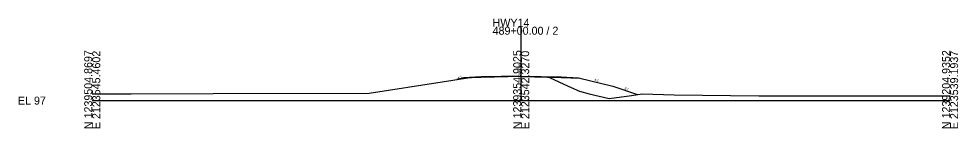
# Model space of a CAD drawing. Extents: x -26 to 303, y -10 to 11521.
# Drawn here: x -25.7 to 302.8, y 490.3 to 528.7 of the extents above; entities that cross this region are included whole.
import ezdxf

# ---------------------------------------------------------------- set-up
doc = ezdxf.new("R2010")
doc.units = 0
for name, color, linetype in [('XS_CELL', 7, 'Continuous'), ('XS_P_FINISHED_GRADE', 7, 'Continuous'), ('XS_P_SUBGRADE_GRANULAR', 7, 'Continuous'), ('XS_P_SUBGRADE_LEVELING', 7, 'Continuous'), ('XS_P_TX_FS_BS', 7, 'Continuous'), ('XS_X_GROUND', 7, 'Continuous'), ('XS_X_GROUND_TX', 7, 'Continuous')]:
    doc.layers.add(name, color=color, linetype=linetype)

msp = doc.modelspace()

# ---------------------------------------------------------------- linework, layer by layer
at = {"layer": 'XS_CELL'}
for p, q in [((150, 500), (150, 525.9)), ((0, 500), (150, 500)), ((150, 500), (300, 500))]:
    msp.add_line(p, q, dxfattribs=at)
at = {"layer": 'XS_P_FINISHED_GRADE'}
for p, q in [((130, 508.04), (127.47, 507.41)), ((136, 508.28), (130, 508.04)), ((150, 508.56), (136, 508.28)), ((150, 508.56), (164, 508.28)), ((164, 508.28), (170, 508.04)), ((170, 508.04), (182, 505.04)), ((182, 505.04), (190.69, 502.14))]:
    msp.add_line(p, q, dxfattribs=at)
at = {"layer": 'XS_P_SUBGRADE_GRANULAR'}
for p, q in [((136, 508.15), (129.4, 507.89)), ((164, 508.15), (170.6, 507.89))]:
    msp.add_line(p, q, dxfattribs=at)
at = {"layer": 'XS_P_SUBGRADE_LEVELING'}
for p, q in [((150, 508.43), (136, 508.15)), ((136, 508.15), (136, 508.28)), ((150, 508.43), (164, 508.15)), ((164, 508.15), (164, 508.28))]:
    msp.add_line(p, q, dxfattribs=at)
at = {"layer": 'XS_X_GROUND'}
for p, q in [((96.86, 502.57), (122.39, 506.62)), ((122.39, 506.62), (132.01, 508.11)), ((132.01, 508.11), (133.97, 508.23)), ((133.97, 508.23), (136.08, 508.37)), ((136.08, 508.37), (145.78, 508.6)), ((145.78, 508.6), (146.99, 508.63)), ((146.99, 508.63), (150, 508.56)), ((150, 508.56), (157.7, 508.37)), ((157.7, 508.37), (158.12, 508.32)), ((158.12, 508.32), (159.93, 508.06)), ((159.93, 508.06), (166.38, 505.09)), ((166.38, 505.09), (170.38, 503.27)), ((170.38, 503.27), (173.8, 502.38)), ((0, 502.4), (13.65, 502.42)), ((13.65, 502.42), (42.33, 502.45)), ((42.33, 502.45), (96.86, 502.57)), ((173.8, 502.38), (180.78, 500.72)), ((180.78, 500.72), (188.63, 501.84)), ((188.63, 501.84), (192.35, 502.39)), ((192.35, 502.39), (203.48, 501.97)), ((203.48, 501.97), (233.1, 501.71)), ((233.1, 501.71), (269.49, 501.63)), ((269.49, 501.63), (300, 501.64))]:
    msp.add_line(p, q, dxfattribs=at)

# ---------------------------------------------------------------- texts
at = {"layer": 'XS_CELL'}
for s, p in [('489+00.00 / 2', (140, 523.1)), ('HWY14', (140, 525.9)), ('EL 97', (-26, 498.6))]:
    msp.add_text(s, height=2.8, dxfattribs=at).set_placement(p)
for s, p in [('N 1239504.8697', (0, 490)), ('E 2123545.4602', (2.8, 490)), ('N 1239354.9025', (150, 490)), ('E 2123542.3270', (152.8, 490)), ('N 1239204.9352', (300, 490)), ('E 2123539.1937', (302.8, 490))]:
    msp.add_text(s, height=2.8, rotation=90, dxfattribs=at).set_placement(p)
at = {"layer": 'XS_P_TX_FS_BS'}
for s, rotation, p in [('4:1', 14.0362, (127.87, 507.63)), ('4:1', 345.9638, (175.56, 507.01)), ('3:1', 341.5651, (186.06, 504.06))]:
    msp.add_text(s, height=0.8, rotation=rotation, dxfattribs=at).set_placement(p)
at = {"layer": 'XS_X_GROUND_TX'}
msp.add_text('105.56', height=1, rotation=90, dxfattribs=at).set_placement((150, 508.66))

doc.saveas('drawing.dxf')
